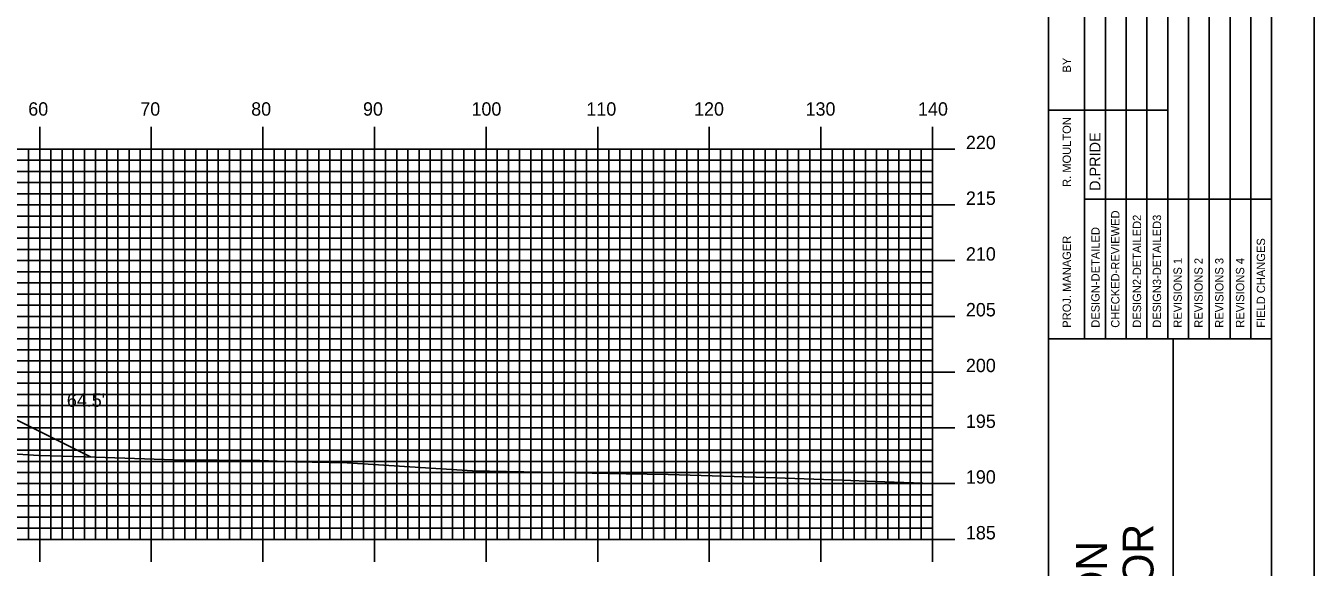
# Model space of a CAD drawing. Extents: x 1812554 to 1812897, y 442591 to 442811.
# Drawn here: x 1812778.7 to 1812894.2, y 442666.2 to 442714.7 of the extents above; entities that cross this region are included whole.
import ezdxf

# ---------------------------------------------------------------- set-up
doc = ezdxf.new("R2010")
doc.units = 0
for name, color, linetype in [('BORDER', 7, 'Continuous'), ('D_Roadway_Centerline', 7, 'Continuous'), ('D_Roadway_SlopeLines', 7, 'Continuous'), ('D_Text_Standard', 7, 'Continuous'), ('H_V ANNOTATION', 7, 'Continuous'), ('MAJOR', 7, 'Continuous'), ('MINOR', 7, 'Continuous'), ('PLOT BOUNDARY', 7, 'Continuous'), ('S_Roadway_Centerline', 7, 'Continuous')]:
    doc.layers.add(name, color=color, linetype=linetype)

msp = doc.modelspace()

# ---------------------------------------------------------------- linework, layer by layer
at = {"layer": 'BORDER'}
for p, q in [((1812870.34, 442596.67), (1812870.34, 442806.67)), ((1812870.34, 442686.67), (1812890.34, 442686.67)), ((1812881.52, 442616.67), (1812881.52, 442686.67))]:
    msp.add_line(p, q, dxfattribs=at)
msp.add_lwpolyline([(1812570.34, 442596.67), (1812890.34, 442596.67), (1812890.34, 442806.67), (1812570.34, 442806.67)], close=True, dxfattribs=at)
for points in [[(1812875.44, 442686.68), (1812875.44, 442721.67)], [(1812877.3, 442721.67), (1812877.3, 442686.68)], [(1812879.16, 442686.68), (1812879.16, 442721.67)], [(1812881.03, 442686.68), (1812881.03, 442721.67)], [(1812882.89, 442686.68), (1812882.89, 442721.67)], [(1812884.75, 442686.68), (1812884.75, 442721.67)], [(1812886.62, 442686.68), (1812886.62, 442721.67)], [(1812888.48, 442686.68), (1812888.48, 442721.67)], [(1812873.57, 442686.68), (1812873.57, 442720.26)], [(1812870.34, 442707.17), (1812873.57, 442707.17)], [(1812873.57, 442707.17), (1812881.03, 442707.17)], [(1812873.57, 442699.17), (1812890.34, 442699.17)]]:
    msp.add_lwpolyline(points, dxfattribs=at)
at = {"layer": 'D_Roadway_Centerline'}
msp.add_lwpolyline([(1812656.82, 442678.23), (1812691.73, 442695.68), (1812696.94, 442698.28), (1812699.94, 442698.34), (1812707.94, 442698.5), (1812719.94, 442697.93), (1812731.94, 442697.35), (1812739.94, 442696.97), (1812742.94, 442696.82), (1812748.47, 442694.06), (1812784.48, 442676.06)], dxfattribs=at)
at = {"layer": 'D_Roadway_SlopeLines'}
msp.add_lwpolyline([(1812742.94, 442696.82), (1812784.48, 442676.06)], dxfattribs=at)
at = {"layer": 'MAJOR'}
for p, q in [((1812779.94, 442705.67), (1812779.94, 442703.67)), ((1812789.94, 442705.67), (1812789.94, 442703.67)), ((1812799.94, 442705.67), (1812799.94, 442703.67)), ((1812809.94, 442705.67), (1812809.94, 442703.67)), ((1812819.94, 442705.67), (1812819.94, 442703.67)), ((1812829.94, 442705.67), (1812829.94, 442703.67)), ((1812839.94, 442705.67), (1812839.94, 442703.67)), ((1812849.94, 442705.67), (1812849.94, 442703.67)), ((1812859.94, 442705.67), (1812859.94, 442703.67)), ((1812579.94, 442703.67), (1812859.94, 442703.67)), ((1812579.94, 442703.67), (1812859.94, 442703.67)), ((1812779.94, 442668.67), (1812779.94, 442703.67)), ((1812789.94, 442668.67), (1812789.94, 442703.67)), ((1812799.94, 442668.67), (1812799.94, 442703.67)), ((1812809.94, 442668.67), (1812809.94, 442703.67)), ((1812819.94, 442668.67), (1812819.94, 442703.67)), ((1812829.94, 442668.67), (1812829.94, 442703.67)), ((1812839.94, 442668.67), (1812839.94, 442703.67)), ((1812849.94, 442668.67), (1812849.94, 442703.67)), ((1812861.95, 442703.67), (1812857.94, 442703.67)), ((1812859.94, 442668.67), (1812859.94, 442703.67)), ((1812859.94, 442668.67), (1812859.94, 442703.67)), ((1812579.94, 442698.67), (1812859.94, 442698.67)), ((1812861.95, 442698.67), (1812857.94, 442698.67)), ((1812579.94, 442693.67), (1812859.94, 442693.67)), ((1812861.95, 442693.67), (1812857.94, 442693.67)), ((1812579.94, 442688.67), (1812859.94, 442688.67)), ((1812861.95, 442688.67), (1812857.94, 442688.67)), ((1812579.94, 442683.67), (1812859.94, 442683.67)), ((1812861.95, 442683.67), (1812857.94, 442683.67)), ((1812579.94, 442678.67), (1812859.94, 442678.67)), ((1812861.95, 442678.67), (1812857.94, 442678.67)), ((1812579.94, 442673.67), (1812859.94, 442673.67)), ((1812861.95, 442673.67), (1812857.94, 442673.67)), ((1812579.94, 442668.67), (1812859.94, 442668.67)), ((1812579.94, 442668.67), (1812859.94, 442668.67)), ((1812779.94, 442666.66), (1812779.94, 442668.67)), ((1812789.94, 442666.66), (1812789.94, 442668.67)), ((1812799.94, 442666.66), (1812799.94, 442668.67)), ((1812809.94, 442666.66), (1812809.94, 442668.67)), ((1812819.94, 442666.66), (1812819.94, 442668.67)), ((1812829.94, 442666.66), (1812829.94, 442668.67)), ((1812839.94, 442666.66), (1812839.94, 442668.67)), ((1812849.94, 442666.66), (1812849.94, 442668.67)), ((1812861.95, 442668.67), (1812857.94, 442668.67)), ((1812859.94, 442666.66), (1812859.94, 442668.67))]:
    msp.add_line(p, q, dxfattribs=at)
at = {"layer": 'MINOR'}
for p, q in [((1812778.94, 442668.67), (1812778.94, 442703.67)), ((1812780.94, 442668.67), (1812780.94, 442703.67)), ((1812781.94, 442668.67), (1812781.94, 442703.67)), ((1812782.94, 442668.67), (1812782.94, 442703.67)), ((1812783.94, 442668.67), (1812783.94, 442703.67)), ((1812784.94, 442668.67), (1812784.94, 442703.67)), ((1812785.94, 442668.67), (1812785.94, 442703.67)), ((1812786.94, 442668.67), (1812786.94, 442703.67)), ((1812787.94, 442668.67), (1812787.94, 442703.67)), ((1812788.94, 442668.67), (1812788.94, 442703.67)), ((1812790.94, 442668.67), (1812790.94, 442703.67)), ((1812791.94, 442668.67), (1812791.94, 442703.67)), ((1812792.94, 442668.67), (1812792.94, 442703.67)), ((1812793.94, 442668.67), (1812793.94, 442703.67)), ((1812794.94, 442668.67), (1812794.94, 442703.67)), ((1812795.94, 442668.67), (1812795.94, 442703.67)), ((1812796.94, 442668.67), (1812796.94, 442703.67)), ((1812797.94, 442668.67), (1812797.94, 442703.67)), ((1812798.94, 442668.67), (1812798.94, 442703.67)), ((1812800.94, 442668.67), (1812800.94, 442703.67)), ((1812801.94, 442668.67), (1812801.94, 442703.67)), ((1812802.94, 442668.67), (1812802.94, 442703.67)), ((1812803.94, 442668.67), (1812803.94, 442703.67)), ((1812804.94, 442668.67), (1812804.94, 442703.67)), ((1812805.94, 442668.67), (1812805.94, 442703.67)), ((1812806.94, 442668.67), (1812806.94, 442703.67)), ((1812807.94, 442668.67), (1812807.94, 442703.67)), ((1812808.94, 442668.67), (1812808.94, 442703.67)), ((1812810.94, 442668.67), (1812810.94, 442703.67)), ((1812811.94, 442668.67), (1812811.94, 442703.67)), ((1812812.94, 442668.67), (1812812.94, 442703.67)), ((1812813.94, 442668.67), (1812813.94, 442703.67)), ((1812814.94, 442668.67), (1812814.94, 442703.67)), ((1812815.94, 442668.67), (1812815.94, 442703.67)), ((1812816.94, 442668.67), (1812816.94, 442703.67)), ((1812817.94, 442668.67), (1812817.94, 442703.67)), ((1812818.94, 442668.67), (1812818.94, 442703.67)), ((1812820.94, 442668.67), (1812820.94, 442703.67)), ((1812821.94, 442668.67), (1812821.94, 442703.67)), ((1812822.94, 442668.67), (1812822.94, 442703.67)), ((1812823.94, 442668.67), (1812823.94, 442703.67)), ((1812824.94, 442668.67), (1812824.94, 442703.67)), ((1812825.94, 442668.67), (1812825.94, 442703.67)), ((1812826.94, 442668.67), (1812826.94, 442703.67)), ((1812827.94, 442668.67), (1812827.94, 442703.67)), ((1812828.94, 442668.67), (1812828.94, 442703.67)), ((1812830.94, 442668.67), (1812830.94, 442703.67)), ((1812831.94, 442668.67), (1812831.94, 442703.67)), ((1812832.94, 442668.67), (1812832.94, 442703.67)), ((1812833.94, 442668.67), (1812833.94, 442703.67)), ((1812834.94, 442668.67), (1812834.94, 442703.67)), ((1812835.94, 442668.67), (1812835.94, 442703.67)), ((1812836.94, 442668.67), (1812836.94, 442703.67)), ((1812837.94, 442668.67), (1812837.94, 442703.67)), ((1812838.94, 442668.67), (1812838.94, 442703.67)), ((1812840.94, 442668.67), (1812840.94, 442703.67)), ((1812841.94, 442668.67), (1812841.94, 442703.67)), ((1812842.94, 442668.67), (1812842.94, 442703.67)), ((1812843.94, 442668.67), (1812843.94, 442703.67)), ((1812844.94, 442668.67), (1812844.94, 442703.67)), ((1812845.94, 442668.67), (1812845.94, 442703.67)), ((1812846.94, 442668.67), (1812846.94, 442703.67)), ((1812847.94, 442668.67), (1812847.94, 442703.67)), ((1812848.94, 442668.67), (1812848.94, 442703.67)), ((1812850.94, 442668.67), (1812850.94, 442703.67)), ((1812851.94, 442668.67), (1812851.94, 442703.67)), ((1812852.94, 442668.67), (1812852.94, 442703.67)), ((1812853.94, 442668.67), (1812853.94, 442703.67)), ((1812854.94, 442668.67), (1812854.94, 442703.67)), ((1812855.94, 442668.67), (1812855.94, 442703.67)), ((1812856.94, 442668.67), (1812856.94, 442703.67)), ((1812857.94, 442668.67), (1812857.94, 442703.67)), ((1812858.94, 442668.67), (1812858.94, 442703.67)), ((1812579.94, 442702.67), (1812859.94, 442702.67)), ((1812859.94, 442702.67), (1812857.94, 442702.67)), ((1812579.94, 442701.67), (1812859.94, 442701.67)), ((1812859.94, 442701.67), (1812857.94, 442701.67)), ((1812579.94, 442700.67), (1812859.94, 442700.67)), ((1812579.94, 442699.67), (1812859.94, 442699.67)), ((1812859.94, 442700.67), (1812857.94, 442700.67)), ((1812859.94, 442699.67), (1812857.94, 442699.67)), ((1812579.94, 442697.67), (1812859.94, 442697.67)), ((1812859.94, 442697.67), (1812857.94, 442697.67)), ((1812579.94, 442696.67), (1812859.94, 442696.67)), ((1812859.94, 442696.67), (1812857.94, 442696.67)), ((1812579.94, 442695.67), (1812859.94, 442695.67)), ((1812859.94, 442695.67), (1812857.94, 442695.67)), ((1812579.94, 442694.67), (1812859.94, 442694.67)), ((1812859.94, 442694.67), (1812857.94, 442694.67)), ((1812579.94, 442692.67), (1812859.94, 442692.67)), ((1812579.94, 442691.67), (1812859.94, 442691.67)), ((1812859.94, 442692.67), (1812857.94, 442692.67)), ((1812859.94, 442691.67), (1812857.94, 442691.67)), ((1812579.94, 442690.67), (1812859.94, 442690.67)), ((1812859.94, 442690.67), (1812857.94, 442690.67)), ((1812579.94, 442689.67), (1812859.94, 442689.67)), ((1812859.94, 442689.67), (1812857.94, 442689.67)), ((1812579.94, 442687.67), (1812859.94, 442687.67)), ((1812859.94, 442687.67), (1812857.94, 442687.67)), ((1812579.94, 442686.67), (1812859.94, 442686.67)), ((1812859.94, 442686.67), (1812857.94, 442686.67)), ((1812579.94, 442685.67), (1812859.94, 442685.67)), ((1812579.94, 442684.67), (1812859.94, 442684.67)), ((1812859.94, 442685.67), (1812857.94, 442685.67)), ((1812859.94, 442684.67), (1812857.94, 442684.67)), ((1812579.94, 442682.67), (1812859.94, 442682.67)), ((1812859.94, 442682.67), (1812857.94, 442682.67)), ((1812579.94, 442681.67), (1812859.94, 442681.67)), ((1812859.94, 442681.67), (1812857.94, 442681.67)), ((1812579.94, 442680.67), (1812859.94, 442680.67)), ((1812859.94, 442680.67), (1812857.94, 442680.67)), ((1812579.94, 442679.67), (1812859.94, 442679.67)), ((1812859.94, 442679.67), (1812857.94, 442679.67)), ((1812579.94, 442677.67), (1812859.94, 442677.67)), ((1812579.94, 442676.67), (1812859.94, 442676.67)), ((1812859.94, 442677.67), (1812857.94, 442677.67)), ((1812859.94, 442676.67), (1812857.94, 442676.67)), ((1812579.94, 442675.67), (1812859.94, 442675.67)), ((1812859.94, 442675.67), (1812857.94, 442675.67)), ((1812579.94, 442674.67), (1812859.94, 442674.67)), ((1812859.94, 442674.67), (1812857.94, 442674.67)), ((1812579.94, 442672.67), (1812859.94, 442672.67)), ((1812859.94, 442672.67), (1812857.94, 442672.67)), ((1812579.94, 442671.67), (1812859.94, 442671.67)), ((1812859.94, 442671.67), (1812857.94, 442671.67)), ((1812579.94, 442670.67), (1812859.94, 442670.67)), ((1812579.94, 442669.67), (1812859.94, 442669.67)), ((1812859.94, 442670.67), (1812857.94, 442670.67)), ((1812859.94, 442669.67), (1812857.94, 442669.67))]:
    msp.add_line(p, q, dxfattribs=at)
at = {"layer": 'PLOT BOUNDARY'}
msp.add_lwpolyline([(1812554.16, 442590.55), (1812894.16, 442590.55), (1812894.16, 442810.55), (1812554.16, 442810.55)], close=True, dxfattribs=at)
at = {"layer": 'S_Roadway_Centerline'}
msp.add_lwpolyline([(1812767.82, 442676.93), (1812779.87, 442676.18), (1812784.05, 442676.07), (1812791.97, 442675.81), (1812799.67, 442675.75), (1812802.79, 442675.63), (1812807.5, 442675.55), (1812818.71, 442674.83), (1812832.49, 442674.56), (1812836.27, 442674.48), (1812844.15, 442674.25), (1812851.9, 442673.97), (1812854.82, 442673.87), (1812859.94, 442673.67)], dxfattribs=at)

# ---------------------------------------------------------------- texts
at = {"layer": 'BORDER'}
for s, height, p in [('BY', 0.743, (1812872.35, 442710.54)), ('R. MOULTON', 0.745, (1812872.35, 442700.28)), ('D.PRIDE', 0.969, (1812874.99, 442699.92)), ('CHECKED-REVIEWED', 0.7455, (1812876.7, 442687.65)), ('DESIGN2-DETAILED2', 0.7455, (1812878.64, 442687.65)), ('DESIGN3-DETAILED3', 0.7455, (1812880.43, 442687.65)), ('DESIGN-DETAILED', 0.7455, (1812874.92, 442687.65)), ('PROJ. MANAGER', 0.7455, (1812872.35, 442687.65)), ('FIELD CHANGES', 0.7455, (1812889.75, 442687.65)), ('REVISIONS 1', 0.7455, (1812882.29, 442687.65)), ('REVISIONS 2', 0.7455, (1812884.16, 442687.65)), ('REVISIONS 3', 0.7455, (1812886.02, 442687.65)), ('REVISIONS 4', 0.7455, (1812887.88, 442687.65)), ('1-395/ROUTE 9 CONNECTOR', 2.7557, (1812879.75, 442618.87)), ('BREWER TO EDDINGTON', 2.7557, (1812875.57, 442623.07))]:
    msp.add_text(s, height=height, rotation=90, dxfattribs=at).set_placement(p)
at = {"layer": 'D_Text_Standard'}
msp.add_text("64.5'", height=1.2, dxfattribs=at).set_placement((1812782.37, 442680.56))
at = {"layer": 'H_V ANNOTATION'}
for s, p in [('60', (1812778.91, 442706.67)), ('70', (1812788.95, 442706.67)), ('80', (1812798.89, 442706.67)), ('90', (1812808.91, 442706.67)), ('100', (1812818.63, 442706.67)), ('110', (1812828.93, 442706.67)), ('120', (1812838.58, 442706.67)), ('130', (1812848.57, 442706.67)), ('140', (1812858.65, 442706.67)), ('220', (1812862.94, 442703.67)), ('215', (1812862.94, 442698.67)), ('210', (1812862.94, 442693.67)), ('205', (1812862.94, 442688.67)), ('200', (1812862.94, 442683.67)), ('195', (1812862.94, 442678.67)), ('190', (1812862.94, 442673.67)), ('185', (1812862.94, 442668.67))]:
    msp.add_text(s, height=1.2, dxfattribs=at).set_placement(p)

doc.saveas('drawing.dxf')
